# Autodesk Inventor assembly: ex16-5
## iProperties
Shininess: 64.0
Length Units: 11269
Angle Units: 11279
Time Units: 11290
Mass Units: 11283
Length Display Precision: 3
Angle Display Precision: 2
Compacted: True
Created: 2002-11
Part Number: ex16-5
Document SubType Name: Assembly
Designer: E. MOSS
Density: 0.0
Volumn: 0.0
Area: 0.0
PropertySet Name: Model Information
Control State: 0
Master: False
Checked Out: False
Author: E. MOSS
